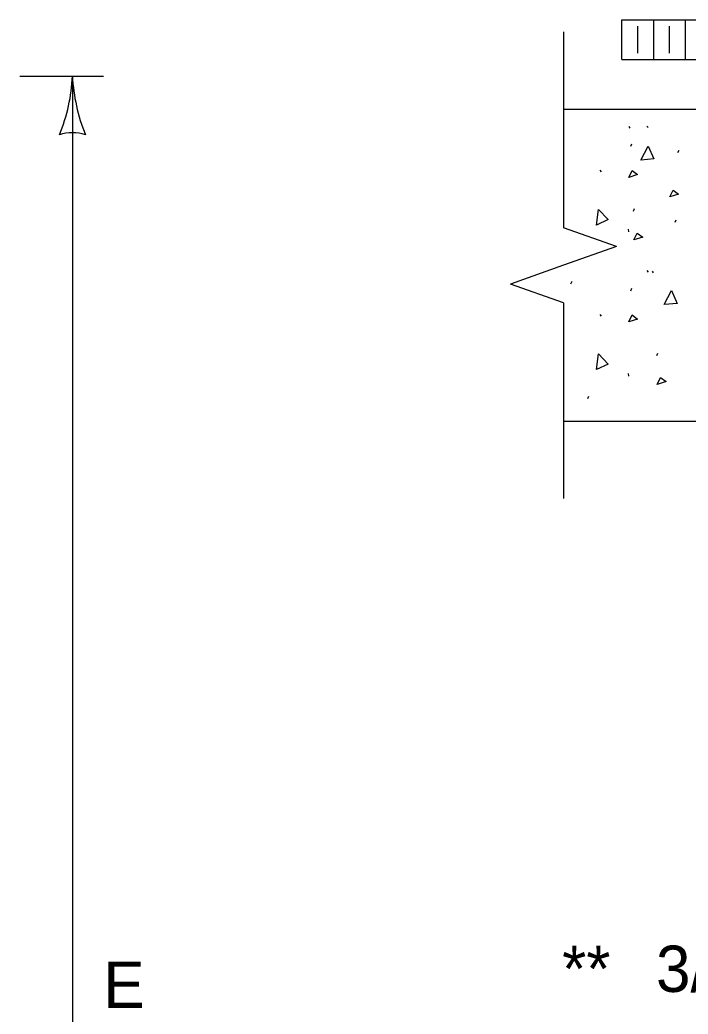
# Model space of a CAD drawing. Extents: x 49991.4 to 50021, y 49987.6 to 50011.4.
# Drawn here: x 50004.619 to 50005.484, y 50002.431 to 50003.719 of the extents above; entities that cross this region are included whole.
import ezdxf

# ---------------------------------------------------------------- set-up
doc = ezdxf.new("R2010")
doc.units = 0
for name, color, linetype in [('Level 1', 7, 'Continuous'), ('Level 2', 7, 'Continuous'), ('Level 3', 7, 'Continuous'), ('Level 6', 7, 'Continuous')]:
    doc.layers.add(name, color=color, linetype=linetype)

msp = doc.modelspace()

# ---------------------------------------------------------------- linework, layer by layer
at = {"layer": 'Level 1'}
for p, q in [((50005.3982, 50003.7186), (50005.497, 50003.7186)), ((50005.3982, 50003.6672), (50005.3982, 50003.7186)), ((50005.4392, 50003.6672), (50005.4392, 50003.7186)), ((50005.4804, 50003.6672), (50005.4804, 50003.7186)), ((50005.4187, 50003.6754), (50005.4187, 50003.7103)), ((50005.4598, 50003.6754), (50005.4598, 50003.7103)), ((50005.3982, 50003.6672), (50005.4973, 50003.6672)), ((50005.3226, 50003.603), (50005.6257, 50003.603)), ((50005.407, 50003.5804), (50005.4084, 50003.5783)), ((50005.4305, 50003.5812), (50005.4319, 50003.5791)), ((50005.4095, 50003.5549), (50005.411, 50003.5581)), ((50005.4705, 50003.5467), (50005.472, 50003.5499)), ((50005.3697, 50003.524), (50005.3712, 50003.5218)), ((50005.413, 50003.471), (50005.4144, 50003.4742)), ((50005.467, 50003.4565), (50005.4684, 50003.4597)), ((50005.4062, 50003.4476), (50005.4066, 50003.4444)), ((50005.4305, 50003.3942), (50005.4319, 50003.3921)), ((50005.4371, 50003.3934), (50005.4385, 50003.3913)), ((50005.3322, 50003.377), (50005.3336, 50003.3802)), ((50005.4095, 50003.3679), (50005.411, 50003.3711)), ((50005.3697, 50003.337), (50005.3712, 50003.3348)), ((50005.4431, 50003.284), (50005.4445, 50003.2872)), ((50005.4062, 50003.2606), (50005.4066, 50003.2574)), ((50005.3541, 50003.2283), (50005.3555, 50003.2315)), ((50008.1718, 50003.1988), (50005.3226, 50003.1988))]:
    msp.add_line(p, q, dxfattribs=at)
for points in [[(50005.4226, 50003.5371), (50005.4322, 50003.5552), (50005.4396, 50003.5385), (50005.423, 50003.5371)], [(50005.407, 50003.5147), (50005.4113, 50003.5236), (50005.4184, 50003.5183), (50005.407, 50003.5147)], [(50005.46, 50003.4893), (50005.4642, 50003.4982), (50005.4713, 50003.4929), (50005.46, 50003.4893)], [(50005.365, 50003.4528), (50005.3678, 50003.4731), (50005.3805, 50003.46), (50005.3653, 50003.4529)], [(50005.4137, 50003.4337), (50005.418, 50003.4426), (50005.4251, 50003.4373), (50005.4137, 50003.4337)], [(50005.4527, 50003.3501), (50005.4623, 50003.3682), (50005.4697, 50003.3515), (50005.453, 50003.3501)], [(50005.407, 50003.3277), (50005.4113, 50003.3366), (50005.4184, 50003.3313), (50005.407, 50003.3277)], [(50005.365, 50003.2658), (50005.3678, 50003.2861), (50005.3805, 50003.273), (50005.3653, 50003.2659)], [(50005.4438, 50003.2467), (50005.4481, 50003.2556), (50005.4552, 50003.2503), (50005.4438, 50003.2467)]]:
    msp.add_lwpolyline(points, dxfattribs=at)
at = {"layer": 'Level 3'}
for p, q in [((50004.6192, 50003.6459), (50004.7272, 50003.6459)), ((50004.6872, 50003.6459), (50004.6872, 50001.2929))]:
    msp.add_line(p, q, dxfattribs=at)
for centre, radius, start, end in [((50004.4651, 50003.6551), 0.2223, 337.456, 357.6395), ((50004.9199, 50003.6574), 0.233, 182.8273, 202.0772), ((50004.6872, 50003.5177), 0.0548, 72.1388, 107.8612)]:
    msp.add_arc(centre, radius, start, end, dxfattribs=at)
at = {"layer": 'Level 6'}
for p, q in [((50005.3226, 50003.703), (50005.3226, 50003.4495)), ((50005.3912, 50003.4252), (50005.3226, 50003.4495)), ((50005.3912, 50003.4252), (50005.3226, 50003.4009)), ((50005.3226, 50003.4009), (50005.254, 50003.3766)), ((50005.3226, 50003.3523), (50005.254, 50003.3766)), ((50005.3226, 50003.3523), (50005.3226, 50003.0988))]:
    msp.add_line(p, q, dxfattribs=at)

# ---------------------------------------------------------------- texts
at = {"layer": 'Level 2'}
for s, p in [('**', (50005.3208, 50002.46)), ('3/4" [M20] FOR 18" [450] TO 54" [1350] EQUIV. SIZE 1" [M24] ', (50005.4422, 50002.46)), ('E', (50004.7272, 50002.4394))]:
    msp.add_text(s, height=0.06, dxfattribs=at).set_placement(p)

doc.saveas('drawing.dxf')
